// Mitsubishi GX Works2 project: MM-40MR-12MT-700-FX-A 例程(LJH)   PLC: FX1S

PROGRAM MAIN
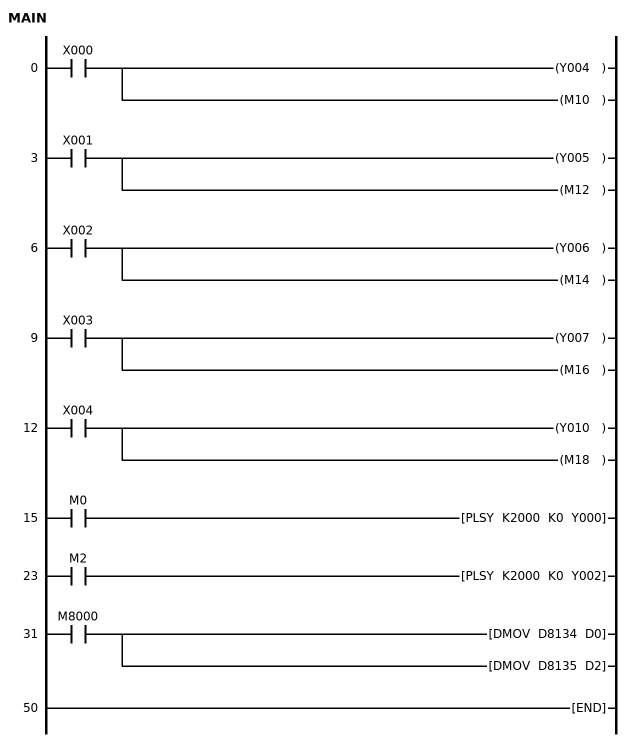
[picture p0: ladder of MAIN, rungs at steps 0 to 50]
0     LD      X000
      OUT     Y004
      OUT     M10
3     LD      X001
      OUT     Y005
      OUT     M12
6     LD      X002
      OUT     Y006
      OUT     M14
9     LD      X003
      OUT     Y007
      OUT     M16
12    LD      X004
      OUT     Y010
      OUT     M18
15    LD      M0
      PLSY    K2000 K0 Y000
23    LD      M2
      PLSY    K2000 K0 Y002
31    LD      M8000
      DMOV    D8134 D0
      DMOV    D8135 D2
50    END
END_PROGRAM
